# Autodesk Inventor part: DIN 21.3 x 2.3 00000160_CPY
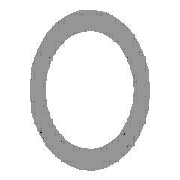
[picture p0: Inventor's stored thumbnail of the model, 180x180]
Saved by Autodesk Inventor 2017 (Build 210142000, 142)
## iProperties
Created: 2017-11
Part Number: DIN 21.3 x 2.3 00000160_CPY
Material: Steel, Mild
Description: Pipe
Document SubType Name: Modeling
Standard: DIN
Designer: iusti
Standard Revision: 2006-07
Standards Organization: DIN
Language: en-US
Size Designation: 21.3 x 2.3
Categories: <MemberInstance><Categories><Category DisplayName="Structural Shapes" InternalName="089c4875-fa83-4c05-b084-43b9cc11f5ed" Mnemonic="GRDR"><CategoryParameter Dis
Stock Number: 21.3 x 2.3
Density: 7.85 g/cm^3
Appearance: Semi-Polished
IsCustomPart: 1
G_L: 500.000 mm
G_W: 21.300 mm
G_H: 21.300 mm
_CCFamilyMember: 1
_CCFamilyDisplayName: DIN EN 10210-2 - Pipe
_FrameMemberDoc: Frame Member File
_Version: 15.0.0
_GetPNFromCC: 1
Author: iusti
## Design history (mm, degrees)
node "Start plane"
node "End plane"
sketch "Sketch"
  geometry: C1 r 8.35 at (0, 0); C2 r 10.65 at (0, 0); 2 further points
  constraints: 3 coincident, 2 centre point
  dimensions: "d0" = 21.3 diameter of C2 (= G_H); "d1" = 2.3 radial gap between concentric circles of C2 C1 (= G_T)
extrude "Body" new body sketch "Sketch" stored distance "d2" = 500 (= G_L); taper "d3" = 0 deg
node "Driven Length"
  sketch "Sketch3"
    geometry: L1 (0, 0)-(10, 0) reference
    constraints: 2 end point, 1 horizontal
  workplane "Work Plane3"
  sketch "Sketch4"
    geometry: L1 (-2, 0)-(12, 0) reference; L2 (-2, 500)-(12, 500) reference
    dimensions: "d7" = 500 distance between parallel lines of L1 L2 (derived)
body "Solid1"
other parameters: "G_H" = 21.3 [user parameter; used in 1 equation term], "G_T" = 2.3 [user parameter; used in 1 equation term], "G_L" = 500 (= d7) [user parameter; used in 1 equation term], "G_OFFSET_START" = 0 [user parameter; used in 1 equation term], "G_OFFSET_END" = 0 [user parameter; used in 1 equation term], "d4" = 0 (computed from G_OFFSET_START), "d6" = 90 deg
